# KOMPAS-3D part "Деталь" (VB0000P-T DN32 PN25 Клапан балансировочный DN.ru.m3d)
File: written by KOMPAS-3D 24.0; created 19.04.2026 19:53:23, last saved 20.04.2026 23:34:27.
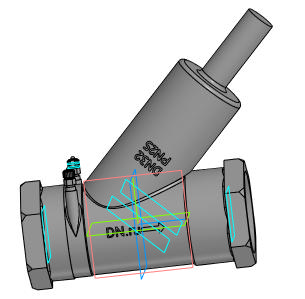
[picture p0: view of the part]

Document properties: Автор: mrdid; Полное имя файла: C:\Работа\VB0000P-T DN X PN 25 Клапан балансировочный DN.ru\DN32\исходные материалы\VB0000P-T DN32 PN25 Клапан балансировочный DN.ru.m3d

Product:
- Body: Тело 1  | qty 1
    Масса: 1.360432
- Body: Тело 2  | qty 1
    Масса: 1.360432
- Body: Тело 3  | qty 1
    Масса: 1.360432
- Body: Тело 4  | qty 1
    Масса: 1.360432
- Part/product: Деталь
    Масса: 0.00084
    Раздел спецификации: Прочие изделия
    Примечание: D080-01177

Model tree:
1. Эскиз:1
2. Элемент вращения:1
     Угол 1 = 360
3. Фаска:1  (with: Ребро.Элемент вращения:1)
     Угол = 45; Длина 1 = 3; Длина 2 = 3
4. Фаска:2  (with: Ребро.Элемент вращения:1)
     Угол = 45; Длина 1 = 2; Длина 2 = 2
5. Фаска:3  (with: Ребро.Элемент вращения:1)
     Угол = 45; Длина 1 = 1; Длина 2 = 1
6. Фаска:4  (with: Ребро.Элемент вращения:1)
     Угол = 30; Длина 1 = 3; Длина 2 = 1.73205
7. Смещенная плоскость:1  (with: Грань.Элемент вращения:1)
     Расстояние = 10
8. Эскиз:2
9. Элемент выдавливания:1  (with: Грань.Фаска:4)
     Расстояние 1 = 55.4195
10. Эскиз:3
11. Элемент выдавливания:2  (with: Грань.Фаска:4)
     Расстояние 2 = 26.4078
12. Смещенная плоскость:2  (with: Грань.Элемент вращения:1)
     Расстояние = 10
13. Эскиз:4  (with: Ребро.Фаска:4)
14. Элемент выдавливания:3  (with: Грань.Фаска:4)
     Расстояние 2 = 55.4195
15. Эскиз:5
16. Элемент выдавливания:4  (with: Грань.Фаска:4)
     Расстояние 2 = 67.4195
17. Фаска:5  (with: Ребро.Элемент выдавливания:4)
     Угол = 45; Длина 1 = 2; Длина 2 = 2
18. Плоскость под углом:1
     Угол = 44
19. Смещенная плоскость:3
     Расстояние = 11
20. Касательная плоскость:1  (with: Грань.Элемент вращения:1)
21. Эскиз:6  (with: Ребро.Фаска:3)
22. Элемент выдавливания:5  (with: Грань.Элемент вращения:1)
     Расстояние 1 = 6.66196; Расстояние 2 = 70
23. Эскиз:7  (with: Грань.Элемент вращения:1)
24. Элемент выдавливания:6  (with: Грань.Элемент вращения:1)
25. Эскиз:8  (with: Грань.Элемент выдавливания:6, Ребро.Элемент выдавливания:6)
26. Элемент выдавливания:7
     Расстояние 1 = 2
27. Эскиз:9  (with: Грань.Элемент выдавливания:7, Ребро.Элемент выдавливания:7)
28. Элемент выдавливания:8
     Расстояние 1 = 1
29. Эскиз:10  (with: Грань.Элемент выдавливания:8, Ребро.Элемент выдавливания:6)
30. Элемент выдавливания:10
     Расстояние 1 = 3
31. Эскиз:11  (with: Грань.Элемент выдавливания:10, Ребро.Элемент выдавливания:6)
32. Элемент выдавливания:11
     Расстояние 1 = 1
33. Эскиз:12  (with: Грань.Элемент выдавливания:11, Ребро.Элемент выдавливания:6)
34. Элемент выдавливания:12
     Расстояние 1 = 3
35. Эскиз:13  (with: Грань.Элемент выдавливания:12, Ребро.Элемент выдавливания:7)
36. Элемент выдавливания:13
     Расстояние 1 = 2
37. Скругление:1  (with: Ребро.Элемент выдавливания:13)
     Радиус = 1
38. Средняя плоскость:2  (with: Грань.Элемент выдавливания:12, Грань.Элемент выдавливания:10)
39. Эскиз:14  (with: Ребро.Элемент выдавливания:11)
40. Элемент выдавливания:14
     Расстояние 1 = 0.5
41. Средняя плоскость:3  (with: Грань.Элемент выдавливания:12)
42. Эскиз:15  (with: Вершина.Элемент выдавливания:14, Ребро.Элемент выдавливания:14)
43. Эскиз:16  (with: Грань.Элемент выдавливания:12, Ребро.Скругление:1)
44. Элемент выдавливания:15
     Расстояние 1 = 0.5
45. Элемент выдавливания:16  (with: Грань.Элемент выдавливания:15, Грань.Элемент выдавливания:14)
     Расстояние 1 = 1.5; Расстояние 2 = 1.75
46. Скругление:2  (with: Ребро.Элемент выдавливания:14, Ребро.Элемент выдавливания:15, Ребро.Элемент выдавливания:16)
     Радиус = 1
47. Зеркальный массив:1
48. Экземпляр ( 1 )
49. Экземпляр ( 2 )  (with: Элемент выдавливания:15, Элемент выдавливания:16, Элемент выдавливания:14, Скругление:2)
50. Скругление:3  (with: Ребро.Элемент выдавливания:5)
     Радиус = 1.5
51. Скругление:4  (with: Ребро.Элемент выдавливания:6)
     Радиус = 1
52. Эскиз:17  (with: Грань.Элемент выдавливания:5, Ребро.Элемент выдавливания:5)
53. Элемент выдавливания:17
     Расстояние 1 = 41
54. Скругление:5  (with: Ребро.Элемент выдавливания:17, Ребро.Элемент выдавливания:5)
     Радиус = 2
55. Скругление:6  (with: Ребро.Элемент выдавливания:2, Ребро.Элемент выдавливания:4)
     Радиус = 1
56. Эскиз:19  (with: Грань.Элемент выдавливания:5)
57. Элемент выдавливания:19  (with: Грань.Элемент выдавливания:5)
     Расстояние 1 = 19.6977; Смещение 1 = 0.2
58. Эскиз:20
59. Элемент выдавливания:20  (with: Грань.Элемент вращения:1)
     Расстояние 1 = 23.2; Смещение 1 = 0.2; Расстояние 2 = 23.2; Смещение 2 = 0.2
60. Эскиз:21
61. Элемент выдавливания:21  (with: Грань.Элемент вращения:1)
     Расстояние 1 = 23.1991; Смещение 1 = 0.2
62. Эскиз:22  (with: Ребро.Фаска:2)
63. Элемент выдавливания:22
     Расстояние 1 = 57; Расстояние 2 = 79.4825

Expressions: 1/2*25.4
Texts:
  Линейный размер с обрывом
  GOST 26.020 Pr3
  var3D
  Dn+1
  Ds-1
  Ds-2
  Ds-4
  Gn+S+5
